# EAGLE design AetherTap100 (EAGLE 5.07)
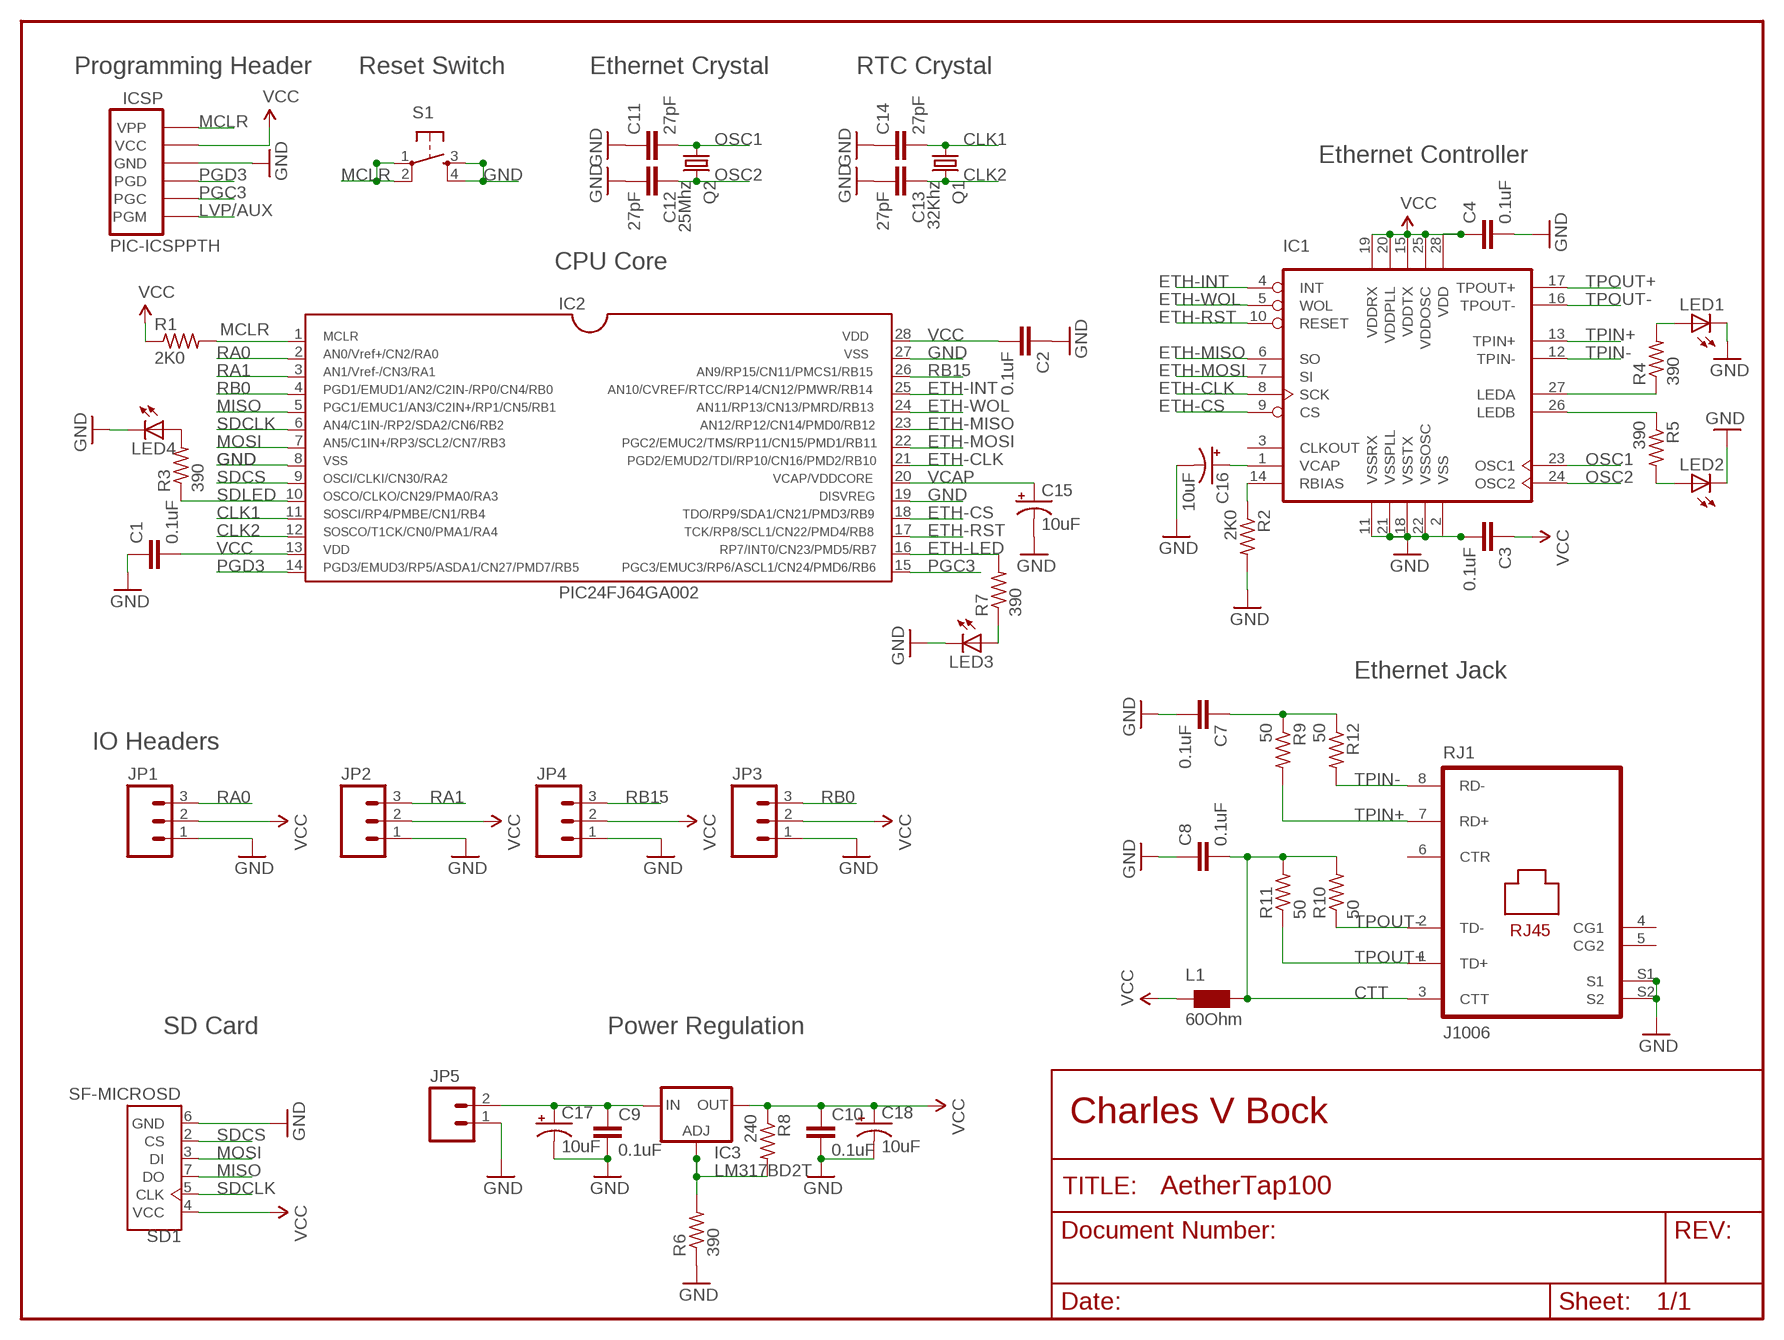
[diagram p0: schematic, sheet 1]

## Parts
C1  0.1uF  CAP0805  [0805]
C2  0.1uF  CAP0805  [0805]
C3  0.1uF  CAP0805  [0805]
C4  0.1uF  CAP0805  [0805]
C7  0.1uF  CAP0805  [0805]
C8  0.1uF  CAP0805  [0805]
C9  0.1uF  CAP0805  [0805]
C10  0.1uF  CAP0805  [0805]
C11  27pF  CAP0805  [0805]
C12  27pF  CAP0805  [0805]
C13  27pF  CAP0805  [0805]
C14  27pF  CAP0805  [0805]
C15  10uF  CAP_POL1206  [EIA3216]
C16  10uF  CAP_POL1206  [EIA3216]
C17  10uF  CAP_POL1206  [EIA3216]
C18  10uF  CAP_POL1206  [EIA3216]
IC1  ENC28J60-SO  [SO28W]
IC2  PIC24FJ64GA002  [SO28W]
IC3  LM317BD2T  [D2PACK]
ICSP  PIC-ICSPPTH  [MOLEX-1X6]
JP1  M03PTH  [1X03]
JP2  M03PTH  [1X03]
JP3  M03PTH  [1X03]
JP4  M03PTH  [1X03]
JP5  M02PTH  [1X02]
L1  60Ohm  WE-KIL_0805  [WE-KI_0805_B]
LED1  LEDCHIPLED_0805  [CHIPLED_0805]
LED2  LEDCHIPLED_0805  [CHIPLED_0805]
LED3  LEDCHIPLED_0805  [CHIPLED_0805]
LED4  LEDCHIPLED_0805  [CHIPLED_0805]
Q1  32Khz  CRYSTALMM20SS  [MM20SS]
Q2  25Mhz  CRYSTALHC49UP  [HC49UP]
R1  2K0  R-US_M0805  [M0805]
R2  2K0  R-US_M0805  [M0805]
R3  390  R-US_M0805  [M0805]
R4  390  R-US_M0805  [M0805]
R5  390  R-US_M0805  [M0805]
R6  390  R-US_M0805  [M0805]
R7  390  R-US_M0805  [M0805]
R8  240  R-US_M0805  [M0805]
R9  50  R-US_M0805  [M0805]
R10  50  R-US_M0805  [M0805]
R11  50  R-US_M0805  [M0805]
R12  50  R-US_M0805  [M0805]
RJ1  J1006  [PJ-J1]
S1  TAC_SWITCHSMD  [TACTILE_SWITCH_SMD]
SD1  SF-MICROSD  [MICROSD]

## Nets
CLK1: C14.2 IC2.11 Q1.1
CLK2: C13.1 IC2.12 Q1.4
CTT: C8.2 L1.1 R10.2 R11.2 RJ1.3(CTT)
ETH-CLK: IC1.8(SCK) IC2.21
ETH-CS: IC1.9(CS) IC2.18
ETH-INT: IC1.4(INT) IC2.25
ETH-LED: IC2.16 R7.2
ETH-MISO: IC1.6(SO) IC2.23
ETH-MOSI: IC1.7(SI) IC2.22
ETH-RST: IC1.10(RESET) IC2.17
ETH-WOL: IC1.5(WOL) IC2.24
GND [GND]: C1.1 C2.1 C3.2 C4.2 C7.2 C8.1 C9.2 C10.2 C11.1 C12.2 C13.2 C14.1 C15.C(-) C16.C(-) C17.C(-) C18.C(-) IC1.2(VSS) IC1.11(VSSRX) IC1.18(VSSTX) IC1.21(VSSPLL) IC1.22(VSSOSC) IC2.8 IC2.19 IC2.27 ICSP.4(GND) JP1.1 JP2.1 JP3.1 JP4.1 JP5.1 LED1.C LED2.C LED3.C LED4.C R2.2 R6.1 RJ1.S1 RJ1.S2 S1.3 S1.4 SD1.6(GND)
LVP/AUX: ICSP.1(PGM)
MCLR: IC2.1 ICSP.6(VPP) R1.2 S1.1 S1.2
MISO: IC2.5 SD1.7(DO)
MOSI: IC2.7 SD1.3(DI)
N$1: LED1.A R4.2
N$2: LED2.A R5.2
N$3: LED3.A R7.1
N$4: C16.A(+) IC1.1(VCAP)
N$5: C9.1 C17.A(+) IC3.3(IN) JP5.2
N$6: IC1.14(RBIAS) R2.1
N$7: IC3.1(ADJ) R6.2 R8.2
N$9: LED4.A R3.2
N$13: C7.1 R9.1 R12.1
N$16: IC1.26(LEDB) R5.1
N$24: IC1.27(LEDA) R4.1
OSC1: C11.2 IC1.23(OSC1) Q2.1
OSC2: C12.1 IC1.24(OSC2) Q2.2
PGC3: IC2.15 ICSP.2(PGC)
PGD3: IC2.14 ICSP.3(PGD)
RA0: IC2.2 JP1.3
RA1: IC2.3 JP2.3
RB0: IC2.4 JP3.3
RB15: IC2.26 JP4.3
SDCLK: IC2.6 SD1.5(CLK)
SDCS: IC2.9 SD1.2(CS)
SDLED: IC2.10 R3.1
TPIN+: IC1.13(TPIN+) R9.2 RJ1.7(RD+)
TPIN-: IC1.12(TPIN-) R12.2 RJ1.8(RD-)
TPOUT+: IC1.17(TPOUT+) R11.1 RJ1.1(TD+)
TPOUT-: IC1.16(TPOUT-) R10.1 RJ1.2(TD-)
VCAP: C15.A(+) IC2.20
VCC [GND]: C1.2 C2.2 C3.1 C4.1 C10.1 C18.A(+) IC1.15(VDDTX) IC1.19(VDDRX) IC1.20(VDDPLL) IC1.25(VDDOSC) IC1.28(VDD) IC2.13 IC2.28 IC3.2(OUT) ICSP.5(VCC) JP1.2 JP2.2 JP3.2 JP4.2 L1.2 R1.1 R8.1 SD1.4(VCC)
Unconnected: IC1.3(CLKOUT) RJ1.4(CG1) RJ1.5(CG2) RJ1.6(CTR)

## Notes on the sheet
- Programming Header | Reset Switch | Ethernet Crystal | RTC Crystal
- Ethernet Controller
- CPU Core
- Ethernet Jack
- IO Headers
- SD Card | Power Regulation
- Charles V Bock

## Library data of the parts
C1-C4 C7-C14 = SparkFun:CAP: Capacitor
C15-C18 = SparkFun:CAP_POL: Capacitor Polarized
IC1 = microchip-enc28j60:ENC28J60-*: Microchip 10Mbit Eth. contoller with SPI interface
IC2 = microchip-pic24:PIC24FJ64GA002
IC3 = v-reg:LM317?*: 500 mA Adjustable Output Positive Voltage Regulator Source: http://www.onsemi.co.jp .. LM317M-D.PDF
ICSP = SparkFun:PIC-ICSP: ISCP Programming connector for UAV, UBW Kit, etc.
JP1-JP4 = SparkFun:M03: Header 3 Standard 3-pin 0.1" header. Use with straight break away headers (SKU : PRT-00116), right angle break away headers (PRT-00553), swiss pins (PRT-00743), machine pins (PRT-00117), and female headers (PRT-00115). Molex polarized connector foot print use with SKU : PRT-08232 with associated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
JP5 = SparkFun:M02: Header 2
L1 = wuerth-elektronik:WE-KIL: SMD Wire Wound Ceramic Inductor WE-KIL
LED1-LED4 = led:LED: LED
Q1 Q2 = crystal:CRYSTAL: CRYSTAL
R1-R12 = resistor:R-US_: RESISTOR, American symbol
RJ1 = con-pulse-j1006:J1006
S1 = SparkFun:TAC_SWITCH: Momentary Switch Button commonly used for reset or general input. Spark Fun Electronics SKU : COM-00097
SD1 = microsd:SF-MICROSD

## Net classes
0 default: width 0.305 mm, clearance 0.254 mm
1 GND: width 0.406 mm, clearance 0.254 mm
2 VCC: width 0.406 mm, clearance 0.254 mm

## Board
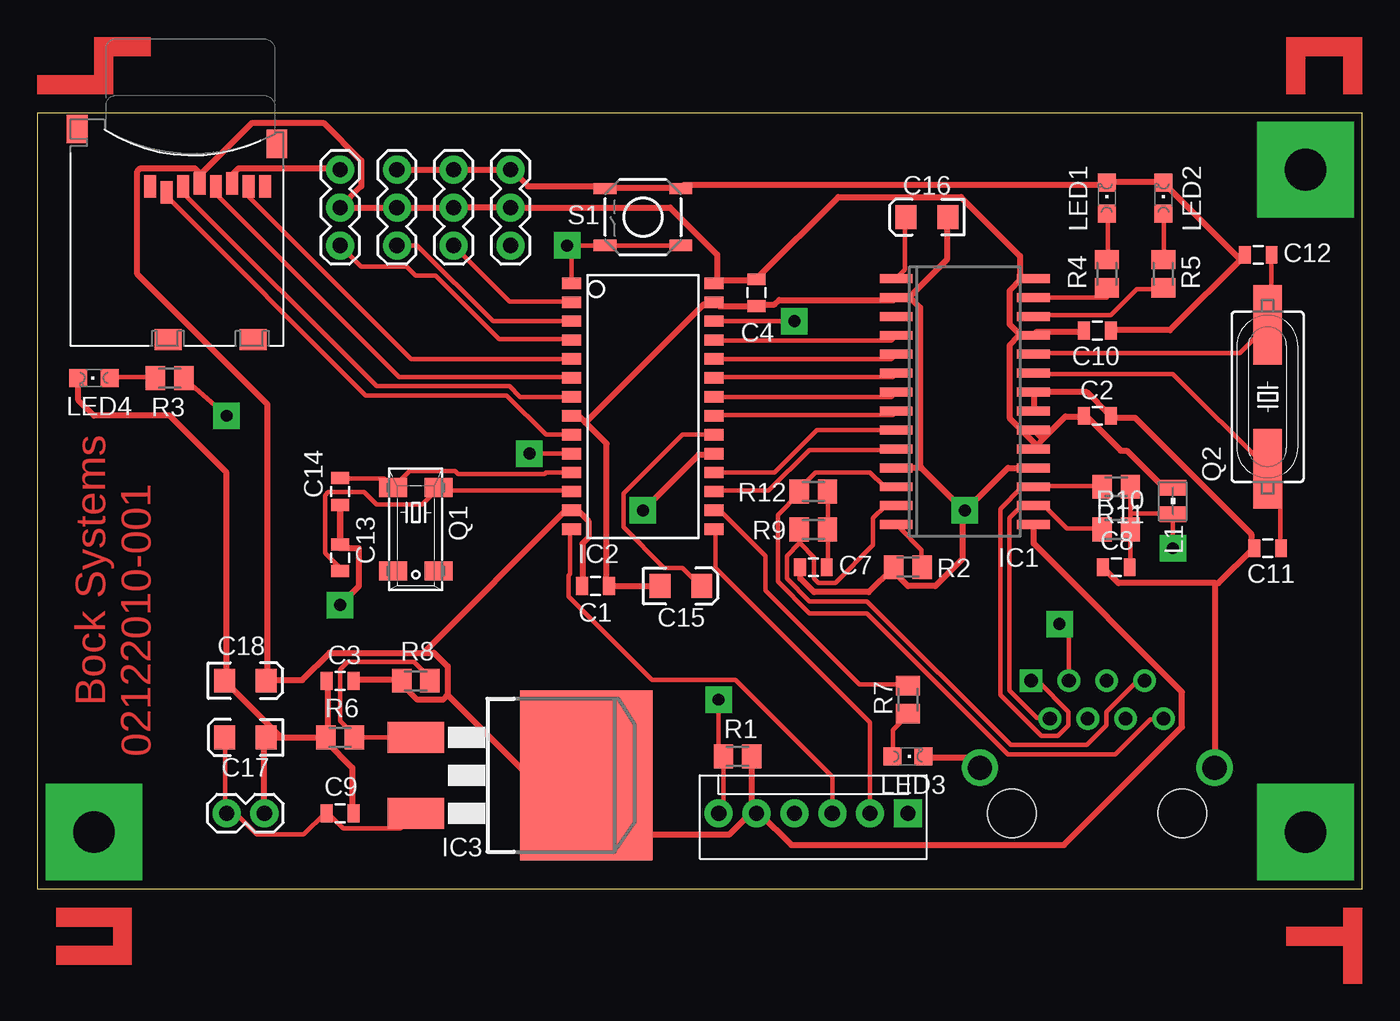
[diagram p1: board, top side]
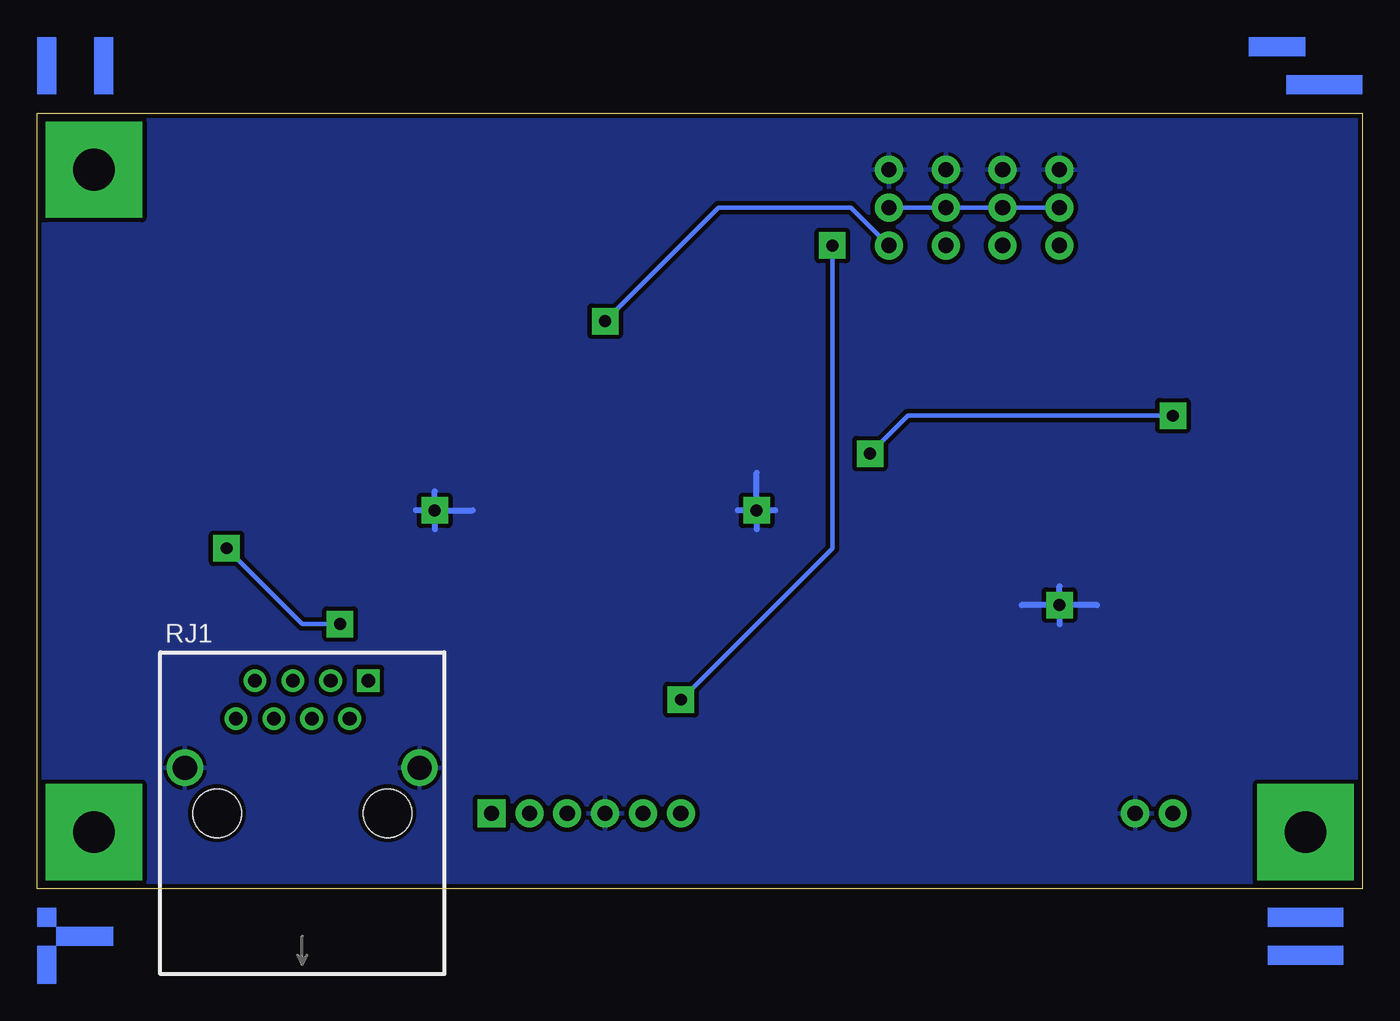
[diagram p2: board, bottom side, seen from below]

Size 88.9 x 52.07 mm. Coordinates in mm from the lower left corner, seen from the top.
Outline: 0,0 88.9,0 88.9,52.07 0,52.07 0,0
Copper layers (1*16): Top 0.035mm / dielectric 1.5mm / Bottom 0.035mm
Design rules "DesignRules *": minimum track width 12mil, minimum drill 20mil, track to track 8mil, track to pad 8mil, pad to pad 8mil, via to via 8mil, smd to smd 8mil, copper to edge 10mil, drill to drill 8mil, minimum pad ring 12mil, minimum via ring 10mil, stop-mask expansion 4mil, vias tented up to drill 25mil, thermal gap 10mil

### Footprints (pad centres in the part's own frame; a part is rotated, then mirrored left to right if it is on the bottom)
0805 = smd 0.8 x 1.2: 1 -0.9,0; 2 0.9,0
EIA3216 = smd 1.4 x 1.6: A 1.4,0; C -1.4,0
SO28W = smd 0.6 x 2.2: 1 -8.255,-4.6; 2 -6.985,-4.6; 3 -5.715,-4.6; 4 -4.445,-4.6; 5 -3.175,-4.6; 6 -1.905,-4.6; 7 -0.635,-4.6; 8 0.635,-4.6; 9 1.905,-4.6; 10 3.175,-4.6; 11 4.445,-4.6; 12 5.715,-4.6; 13 6.985,-4.6; 14 8.255,-4.6; 15 8.255,4.6; 16 6.985,4.6; 17 5.715,4.6; 18 4.445,4.6; 19 3.175,4.6; 20 1.905,4.6; 21 0.635,4.6; 22 -0.635,4.6; 23 -1.905,4.6; 24 -3.175,4.6; 25 -4.445,4.6; 26 -5.715,4.6; 27 -6.985,4.6; 28 -8.255,4.6
SO28W' = smd 0.762 x 1.27: 1 -8.89,-4.78; 2 -7.62,-4.78; 3 -6.35,-4.78; 4 -5.08,-4.78; 5 -3.81,-4.78; 6 -2.54,-4.78; 7 -1.27,-4.78; 8 0,-4.78; 9 1.27,-4.78; 10 2.54,-4.78; 11 3.81,-4.78; 12 5.08,-4.78; 13 6.35,-4.78; 14 7.62,-4.78; 15 7.62,4.78; 16 6.35,4.78; 17 5.08,4.78; 18 3.81,4.78; 19 2.54,4.78; 20 1.27,4.78; 21 0,4.78; 22 -1.27,4.78; 23 -2.54,4.78; 24 -3.81,4.78; 25 -5.08,4.78; 26 -6.35,4.78; 27 -7.62,4.78; 28 -8.89,4.78
D2PACK = smd 2.083 x 3.81: 1 -2.54,-8.89; 3 2.54,-8.89 | smd 11.43 x 8.89: 2 0,2.54
MOLEX-1X6 = drill 1.016 pad 1.88 square: 1 0,0 | drill 1.016 pad 1.88 round: 2 2.54,0; 3 5.08,0; 4 7.62,0; 5 10.16,0; 6 12.7,0
1X03 = drill 1.016 pad 1.88 round: 1 0,0; 2 2.54,0; 3 5.08,0
1X02 = drill 1.016 pad 1.88 round: 1 0,0; 2 2.54,0
WE-KI_0805_B = smd 1.02 x 1.78: 1 -0.89,0; 2 0.89,0
CHIPLED_0805 = smd 1.2 x 1.2: A 0,-1.05; C 0,1.05
MM20SS = smd 1.27 x 1.88: 1 -2.794,-1.524; 2 2.794,-1.524; 3 2.794,1.524; 4 -2.794,1.524
HC49UP = smd 5.334 x 1.93: 1 -4.826,0; 2 4.826,0
M0805 = smd 1.3 x 1.6: 1 -0.95,0; 2 0.95,0
PJ-J1 = drill 0.914 square: 1 4.445,8.89 | drill 0.914 round: 2 3.175,6.35; 3 1.905,8.89; 4 0.635,6.35; 5 -0.635,8.89; 6 -1.905,6.35; 7 -3.175,8.89; 8 -4.445,6.35 | drill 1.626 round: S1 7.874,3.048; S2 -7.874,3.048 | hole 3.251: 5.715,0; -5.715,0
TACTILE_SWITCH_SMD = smd 1.524 x 0.762: 1 -2.54,1.905; 2 2.54,1.905; 3 -2.54,-1.905; 4 2.54,-1.905
MICROSD = smd 0.8 x 1.5: 1 -1.94,2.7; 2 -0.84,2.3; 3 0.26,2.7; 4 1.36,2.9; 5 2.46,2.7; 6 3.56,2.9; 7 4.66,2.7; 8 5.76,2.7 | smd 1.4 x 1.9: NC -6.85,6.55; NC3 6.55,5.55 | smd 1.8 x 1.4: NC1 -0.75,-7.6; NC2 4.95,-7.6

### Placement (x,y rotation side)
C1  37.47,20.32 180 top
C2  71.12,31.75 180 top
C3  20.32,13.97 180 top
C4  48.26,40.01 270 top
C7  52.07,21.59 180 top
C8  72.39,21.59 0 top
C9  20.32,5.08 0 top
C10  71.12,37.47 0 top
C11  82.55,22.86 0 top
C12  81.92,42.55 180 top
C13  20.32,22.23 90 top
C14  20.32,26.67 90 top
C15  43.18,20.32 0 top
C16  59.69,45.09 180 top
C17  13.97,10.16 180 top
C18  13.97,13.97 0 top
IC1  62.23,32.7 270 top
IC2  PIC24FJ64GA002  [SO28W']  40.64,31.75 270 top
IC3  34.29,7.62 270 top
ICSP  58.42,5.08 180 top
JP1  27.94,48.26 270 top
JP2  24.13,48.26 270 top
JP3  20.32,48.26 270 top
JP4  31.75,48.26 270 top
JP5  15.24,5.08 180 top
L1  76.2,26.04 90 top
LED1  71.75,46.35 0 top
LED2  75.56,46.35 0 top
LED3  58.42,8.89 270 top
LED4  3.81,34.29 90 top
Q1  25.4,24.13 270 top
Q2  82.55,33.02 90 top
R1  46.99,8.89 180 top
R2  58.42,21.59 180 top
R3  8.89,34.29 180 top
R4  71.75,41.27 90 top
R5  75.56,41.27 90 top
R6  20.32,10.16 0 top
R7  58.42,12.7 90 top
R8  25.4,13.97 0 top
R9  52.07,24.13 180 top
R10  72.39,24.13 0 top
R11  72.39,26.99 0 top
R12  52.07,26.67 180 top
RJ1  71.12,5.08 0 bottom
S1  40.64,45.09 180 top
SD1  9.53,44.45 0 top

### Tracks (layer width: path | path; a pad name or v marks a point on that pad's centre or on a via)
CLK1
  Top 0.305: C14.2 20.32,27.53 23.27,27.53 Q1.1 24.99,28.04 28.04,28.04 28.25,27.84 34.04,27.84 34.14,27.94 IC2.11
CLK2
  Top 0.305: C13.1 20.32,21.54 19.3,22.55 19.3,26.42 19.51,26.62 21.95,26.62 22.76,25.81 25.81,25.81 Q1.4 26.92,26.72 35.76,26.72 IC2.12
CTT  (via drill 0.8 pad 1.78)
  Top 0.305: C8.2 73.36,21.64 73.36,24.08 R10.2 73.36,24.28 73.36,25.2 | 73.36,25.2 73.36,26.92 R11.2 | 73.36,25.2 76.2,25.2 L1.1 v76.2,22.86 | RJ1.3 69.22,17.14 v68.58,17.78
  Bottom 0.305: v68.58,17.78 71.12,17.78 v76.2,22.86
ETH-CLK
  Top 0.305: IC2.21 45.52,31.8 57.4,31.8 57.61,32 IC1.8
ETH-CS
  Top 0.305: IC2.18 49.48,27.94 52.32,30.79 57.61,30.79 IC1.9
ETH-INT
  Top 0.305: IC2.25 45.52,36.78 57.3,36.78 57.61,37.08 IC1.4
ETH-LED
  Top 0.305: IC2.16 45.82,25.4 48.87,22.35 48.87,20.02 55.17,13.72 58.42,13.72 R7.2
ETH-MISO
  Top 0.305: IC2.23 45.52,34.34 57.4,34.34 57.61,34.54 IC1.6
ETH-MOSI
  Top 0.305: IC2.22 57.3,33.02 57.61,33.33 IC1.7
ETH-RST
  Top 0.305: IC2.17 45.52,26.72 49.07,26.72 51.82,29.46 57.61,29.46 IC1.10
ETH-WOL
  Top 0.305: IC2.24 57.3,35.56 57.61,35.87 IC1.5
GND  (via drill 0.8 pad 1.78)
  Top 0.406: C15.C C1.1 38.2,20.42 38.2,29.87 36.78,31.29 | 36.78,31.29 36.37,31.7 35.87,31.7 IC2.8 | C16.C 61.06,45.01 61.06,42.27 58.52,39.73 57.71,39.73 IC1.2 | IC1.2 57.51,39.52 49.78,39.52 49.48,39.22 48.36,39.22 C4.2 45.72,39.12 45.52,39.32 IC2.27 45.31,39.22 44.7,39.22 36.78,31.29 | C10.2 72.03,37.49 76,37.49 80.97,42.47 C12.2 80.67,42.27 75.69,47.24 LED2.C 75.49,47.45 71.83,47.45 LED1.C 71.63,47.24 43.38,47.24 43.28,47.14 S1.3 43.18,47.04 38.1,47.04 S1.4 38,47.14 32.92,47.14 31.8,48.26 JP4.1 JP2.1 | IC1.21 66.85,32.11 66.85,33.12 IC1.22 66.85,33.33 70.41,33.33 71.93,31.8 C2.1 72.14,31.6 73.66,31.6 81.48,23.77 81.48,22.96 C11.1 81.58,22.86 79.25,20.52 79.05,20.52 | C9.2 21.13,5.08 21.13,8.13 19.41,9.86 19.41,10.16 R6.1 | C3.2 19.51,13.92 19.51,10.26 R6.1 | 16.26,10.16 C17.C 15.24,10.06 JP5.1 | 16.26,10.16 R6.1 | 16.26,10.16 16.26,10.26 12.6,13.92 C18.C 12.7,14.1 12.7,27.94 8.89,31.75 3.81,31.75 2.76,32.8 LED4.C | C13.2 C14.1 20.32,22.86 21.59,22.86 21.59,20.32 v20.32,19.05 | LED3.C 59.54,8.84 62.48,8.84 63.2,8.13 RJ1.S1 | v40.64,25.4 44.4,29.16 45.41,29.16 IC2.19 | 59.23,28.25 59.33,28.25 62.18,25.4 v62.23,25.4 | 59.23,28.25 57.71,28.25 IC1.11 | IC1.18 66.75,28.25 65.13,28.25 62.38,25.5 v62.23,25.4 | 78.94,8.13 RJ1.S2 79.05,8.23 79.05,20.52 | IC1.2 58.62,39.62 59.23,39.01 59.23,28.25 | v62.23,25.4 62.08,25.3 | C7.2 51.21,21.54 51.21,20.83 52.12,19.91 55.78,19.91 57.4,21.54 R2.2 57.4,21.34 58.42,20.32 60.25,20.32 62.08,22.15 62.08,25.09 v62.23,25.4 | 79.05,20.52 72.54,20.52 71.53,21.54 C8.1 | JP3.1 20.22,48.36 13.51,48.36 13.11,47.95 13.11,47.45 SD1.6
  Bottom 0.406: 17.78,19.05 v20.32,19.05 | v20.32,19.05 22.86,19.05 | v20.32,19.05 20.32,20.32 | v20.32,19.05 20.32,17.78 | v40.64,25.4 40.64,27.94 | v40.64,25.4 40.64,24.13 | 39.37,25.4 v40.64,25.4 | v40.64,25.4 41.91,25.4 | v62.23,25.4 59.69,25.4 | v62.23,25.4 63.5,25.4 | v62.23,25.4 62.23,26.67 | v62.23,25.4 62.23,24.13
  pour Bottom (isolate 0.305): 0,57.15 0,0 88.9,0 88.9,57.15
MCLR  (via drill 0.8 pad 1.78)
  Top 0.305: ICSP.6 46.04,5.4 R1.2 45.72,9.21 v45.72,12.7 | IC2.1 35.87,43.08 v35.56,43.18 S1.2 S1.1
  Bottom 0.305: v45.72,12.7 35.56,22.86 v35.56,43.18
MISO
  Top 0.305: IC2.5 25.09,35.56 14.22,46.43 14.22,47.14 SD1.7
MOSI
  Top 0.305: IC2.7 32.41,33.02 31.7,33.73 22.76,33.73 9.86,46.63 9.86,47.14 SD1.3
N$1
  Top 0.305: LED1.A 71.83,45.21 71.83,42.27 R4.2
N$2
  Top 0.305: LED2.A 75.59,45.21 75.59,42.27 R5.2
N$3
  Top 0.305: LED3.A 57.4,8.94 57.4,10.67 58.42,11.68 R7.1
N$4
  Top 0.305: C16.A 58.22,45.01 58.22,41.55 57.71,41.05 IC1.1
N$5
  Top 0.305: C17.A 12.6,10.16 12.6,5.18 JP5.2 12.8,4.98 13.41,4.98 14.73,3.66 17.88,3.66 19.3,5.08 C9.1 19.51,5.08 20.52,4.06 24.38,4.06 IC3.3
N$6
  Top 0.305: 57.71,24.38 IC1.14 57.81,24.28 59.33,22.76 59.33,21.64 R2.1
N$7
  Top 0.305: IC3.1 R6.2 21.34,10.26 20.32,11.28 20.32,14.73 20.83,15.24 25.3,15.24 26.31,14.22 26.31,14.02 R8.2
N$8  (via drill 2.8 pad 6.45)
  other vias: 85.09,48.26
N$9
  Top 0.305: LED4.A 4.88,34.34 7.92,34.34 R3.2
N$10  (via drill 2.8 pad 6.45)
  other vias: 85.09,3.81
N$11  (via drill 0.8 pad 1.78)
  other vias: 20.32,19.05
N$12  (via drill 2.8 pad 6.45)
  other vias: 3.81,3.81
N$13
  Top 0.305: C7.1 53.03,21.64 53.03,24.08 R9.1 53.03,24.28 53.03,26.62 R12.1
N$14  (via drill 0.8 pad 1.78)
  other vias: 40.64,25.4
N$15  (via drill 0.8 pad 1.78)
  other vias: 62.23,25.4
N$16
  Top 0.305: R5.1 75.49,40.23 73.76,40.23 72.03,38.51 66.85,38.51 IC1.26
N$24
  Top 0.305: IC1.27 71.75,39.69 R4.1
OSC1
  Top 0.305: C11.2 83.41,22.86 83.41,27.33 Q2.1 76.2,34.54 66.85,34.54 IC1.23
OSC2
  Top 0.305: C12.1 82.8,42.47 82.8,38.1 Q2.2 80.67,35.97 66.85,35.97 IC1.24
PGC3
  Top 0.305: ICSP.2 55.88,11.18 45.52,21.54 45.52,24.08 IC2.15
PGD3
  Top 0.305: ICSP.3 53.34,7.52 46.84,14.02 41.25,14.02 35.66,19.61 35.66,21.03 35.76,21.13 35.76,24.08 IC2.14
RA0
  Top 0.305: JP1.3 31.7,39.42 35.76,39.42 IC2.2
RA1
  Top 0.305: IC2.3 30.58,38.1 25.5,43.18 JP2.3
RB0
  Top 0.305: JP3.3 21.74,41.76 24.79,41.76 25.4,41.15 26.72,41.15 30.99,36.88 35.76,36.88 IC2.4
RB15  (via drill 0.8 pad 1.78)
  Top 0.305: v50.8,38.1 IC2.26
  Bottom 0.305: v50.8,38.1 43.18,45.72 34.29,45.72 JP4.3
SDCLK
  Top 0.305: IC2.6 35.76,34.34 24.28,34.34 11.99,46.63 SD1.5
SDCS
  Top 0.305: IC2.9 34.14,30.48 31.5,33.12 22.05,33.12 8.74,46.43 8.74,46.74 SD1.2
SDLED  (via drill 0.8 pad 1.78)
  Top 0.305: v33.02,29.21 IC2.10 | R3.1 v12.7,31.75
  Bottom 0.305: v33.02,29.21 30.48,31.75 v12.7,31.75
TPIN+
  Top 0.305: 51.21,23.16 51.21,24.08 R9.2 | 51.21,23.16 52.12,22.25 52.12,20.83 52.43,20.52 53.54,20.52 56.08,23.06 56.08,24.89 56.9,25.7 57.61,25.7 IC1.13 | RJ1.7 74.27,13.92 73.76,13.92 71.73,11.89 71.73,10.97 70.41,9.65 65.33,9.65 55.68,19.3 51.82,19.3 50.29,20.83 50.29,22.35 51.1,23.16 51.21,23.16
TPIN-
  Top 0.305: IC1.12 57.61,27.03 56.79,27.03 55.88,27.94 52.22,27.94 51.21,26.92 51.21,26.72 R12.2 51.1,26.52 49.68,25.09 49.68,20.62 51.82,18.49 55.68,18.49 65.13,9.04 72.34,9.04 74.68,11.38 75.49,11.38 RJ1.8
TPOUT+
  Top 0.305: R11.1 71.42,27.03 66.85,27.03 IC1.17 66.75,26.92 66.04,26.92 64.62,25.5 64.62,13.01 67.36,10.26 68.48,10.26 69.19,10.97 69.19,11.89 67.16,13.92 66.75,13.92 RJ1.1
TPOUT-
  Top 0.305: R10.1 71.42,24.18 69.09,24.18 67.56,25.7 66.85,25.7 IC1.16 66.75,25.6 65.94,25.6 65.23,24.89 65.23,13.31 67.06,11.48 67.87,11.48 RJ1.2
VCAP
  Top 0.305: IC2.20 43.28,30.48 39.32,26.52 39.32,24.28 42.06,21.54 43.28,21.54 44.5,20.32 C15.A
VCC
  Top 0.406: ICSP.5 47.95,5.38 47.95,8.84 R1.1 | C1.2 36.58,23.16 36.98,23.57 36.98,24.69 36.27,25.4 IC2.13 35.46,25.4 26.01,15.95 26.01,15.85 | C3.1 21.23,14.02 24.38,14.02 R8.1 24.38,13.82 25.5,12.7 27.23,12.7 27.53,13.01 | 26.01,15.85 26.62,15.85 27.53,14.94 27.53,13.01 | 26.01,15.85 19.61,15.85 17.78,14.02 15.44,14.02 C18.A 15.44,14.22 15.44,32.51 6.71,41.25 6.71,48.16 6.91,48.36 10.57,48.36 10.87,48.06 SD1.4 10.97,47.45 10.97,47.95 14.43,51.41 19.2,51.41 21.74,48.87 21.74,47.14 JP3.2 JP2.2 JP1.2 JP4.2 42.47,45.72 45.62,42.57 45.62,40.95 IC2.28 45.52,40.64 45.72,40.84 48.26,40.84 C4.1 48.36,41.05 53.75,46.43 61.98,46.43 65.94,42.47 65.94,41.05 IC1.28 66.75,40.95 66.04,40.95 65.23,40.13 65.23,37.9 65.94,37.19 66.65,37.19 IC1.25 | 27.53,13.01 32.92,7.62 IC3.2 36.98,7.52 40.84,3.66 46.43,3.66 47.95,5.18 ICSP.5 | C10.1 70.21,37.39 67.06,37.39 66.85,37.19 IC1.25 | 67.06,29.77 66.85,29.57 IC1.19 | 67.06,29.77 67.46,30.18 | 67.46,30.18 68.99,31.7 70.21,31.7 C2.2 70.41,31.7 72.69,29.41 73.1,29.41 75.49,27.03 76.2,27.03 L1.2 | IC1.20 66.85,30.79 67.46,30.18 | IC1.25 65.84,37.08 65.23,36.47 65.23,31.6 67.06,29.77 | IC1.15 66.85,24.38 66.85,23.16 76.81,13.21 76.81,10.87 68.89,2.95 50.6,2.95 48.46,5.08 ICSP.5
  Bottom 0.305: JP3.2 JP4.2
(copper drawn outside any net)
  shapes: Bottom area x10, Top area x11

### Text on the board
Top: Bock Systems | 02122010-001
tTest: 1 | 2 | 3 | 4 | - | + | IO | VIN | GND | 1 | ICSP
